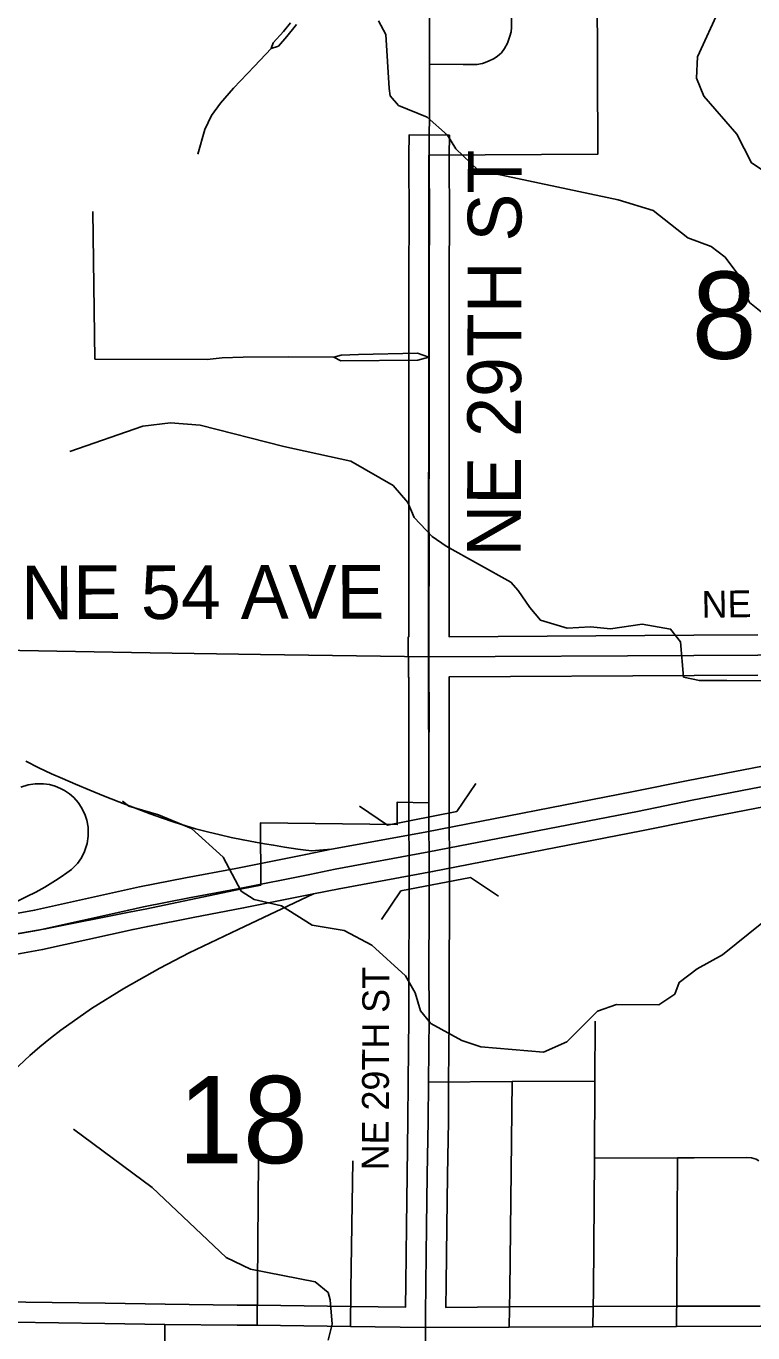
# Model space of a CAD drawing. Extents: x -1403959 to 81668, y -1400582 to 11018.
# Drawn here: x 7427.2 to 7531.9, y 8619.7 to 8808.1 of the extents above; entities that cross this region are included whole.
import ezdxf

# ---------------------------------------------------------------- set-up
doc = ezdxf.new("R2010")
doc.units = 0
for name, color, linetype in [('tdCiAirportTxt', 7, 'Continuous'), ('tdCiCityCartoShort', 7, 'Continuous'), ('tdCiCityDivCarto', 7, 'Continuous'), ('tdCiCoBndryTxt', 7, 'Continuous'), ('tdCiRRCL', 7, 'Continuous'), ('tdCiSectLine', 7, 'Continuous'), ('tdCiSectNmbr', 7, 'Continuous'), ('tdCiSectTwpRng', 7, 'Continuous'), ('tdCoPriCL', 7, 'Continuous'), ('tdCoSectLinePart', 7, 'Continuous'), ('tdCoSectNmbr', 7, 'Continuous'), ('tdCoSurfBitum', 7, 'Continuous'), ('tdCoSurfEarth', 7, 'Continuous')]:
    doc.layers.add(name, color=color, linetype=linetype)

msp = doc.modelspace()

# ---------------------------------------------------------------- linework, layer by layer
at = {"layer": 'tdCiAirportTxt'}
for points in [[(7416.8, 8678.77), (7423.36, 8679.72), (7428.41, 8680.61), (7441.36, 8683.49), (7443.53, 8683.97), (7450.14, 8685.25), (7457.39, 8686.63), (7467.46, 8688.65), (7471.16, 8689.39), (7484.66, 8691.88), (7514.67, 8697.73), (7522.55, 8699.33), (7547.93, 8704.23), (7560.49, 8706.69), (7568.14, 8708.19)], [(7416.8, 8672.91), (7424.28, 8673.99), (7429.55, 8674.92), (7442.6, 8677.83), (7444.7, 8678.28), (7451.24, 8679.55), (7458.5, 8680.93), (7468.6, 8682.95), (7472.26, 8683.69), (7485.74, 8686.18), (7515.8, 8692.04), (7523.68, 8693.64), (7549.04, 8698.53), (7561.6, 8701), (7570.86, 8702.8)]]:
    msp.add_lwpolyline(points, dxfattribs=at)
at = {"layer": 'tdCiCityCartoShort'}
msp.add_lwpolyline([(7581.35, 8707.79), (7561.04, 8703.82), (7548.48, 8701.35), (7523.11, 8696.45), (7515.23, 8694.86), (7485.19, 8689), (7471.7, 8686.51), (7468.03, 8685.77), (7457.94, 8683.75), (7450.69, 8682.37), (7444.11, 8681.09), (7441.98, 8680.63), (7428.98, 8677.74), (7423.8, 8676.82), (7414.4, 8675.33)], dxfattribs=at)
at = {"layer": 'tdCiCityDivCarto'}
for points in [[(7508.81, 8620.55), (7508.89, 8625.89), (7509.06, 8644.86), (7509.08, 8655.94), (7509.13, 8664.61)], [(7485.14, 8655.82), (7497.18, 8655.9), (7509.08, 8655.94)], [(7496.76, 8620.51), (7496.85, 8625.88), (7497.18, 8655.9)], [(7460.48, 8620.78), (7460.67, 8644.58)], [(7473.91, 8620.58), (7473.96, 8625.94), (7474.25, 8644.47)], [(7509.06, 8644.86), (7521.03, 8644.89)], [(7520.84, 8620.61), (7520.89, 8625.89), (7521.03, 8644.89)], [(7521.03, 8644.89), (7523.4, 8644.92), (7530.88, 8644.96), (7531.66, 8644.89), (7532.32, 8644.73), (7532.73, 8644.47)], [(7447.11, 8596.78), (7447.19, 8620.88)]]:
    msp.add_lwpolyline(points, dxfattribs=at)
at = {"layer": 'tdCiCoBndryTxt'}
for points in [[(7485.21, 8696.1), (7485.21, 8702.59), (7485.23, 8709.86), (7485.21, 8714.28), (7485.21, 8717.12), (7485.21, 8722.89), (7485.23, 8731.67), (7485.21, 8738.54), (7485.23, 8746.99), (7485.23, 8756.02), (7485.23, 8760.33), (7485.23, 8764.26), (7485.23, 8772.68), (7485.27, 8780.18), (7485.23, 8789.15), (7485.23, 8789.45)], [(7485.14, 8717.12), (7485.21, 8717.12), (7485.21, 8717.12)], [(7485.21, 8717.12), (7523.38, 8717.35), (7532.58, 8717.39), (7538.9, 8717.43), (7546.99, 8717.49), (7554.11, 8717.56), (7563.63, 8717.64), (7564.75, 8717.65)], [(7485.14, 8655.82), (7485.23, 8665.03), (7485.21, 8672.99), (7485.25, 8679.76), (7485.25, 8686.75), (7485.21, 8694.46), (7485.21, 8696.08)], [(7485.21, 8696.08), (7485.21, 8696.1)], [(7484.52, 8597.05), (7484.61, 8605.17), (7484.64, 8607.27), (7484.66, 8613.68), (7484.7, 8620.43), (7484.71, 8622.3), (7484.77, 8626.75), (7484.87, 8634.99), (7484.96, 8642.42), (7485.1, 8650.26), (7485.14, 8655.82)], [(7411.77, 8621.39), (7438.52, 8621.04), (7447.19, 8620.88), (7457.57, 8620.76), (7460.48, 8620.78)], [(7460.48, 8620.78), (7473.91, 8620.58), (7484.61, 8620.43), (7484.7, 8620.43), (7496.76, 8620.51), (7496.76, 8620.51)], [(7496.76, 8620.51), (7508.81, 8620.55), (7520.84, 8620.61), (7532.91, 8620.64), (7539, 8620.66), (7545.33, 8620.7)]]:
    msp.add_lwpolyline(points, dxfattribs=at)
at = {"layer": 'tdCiRRCL'}
msp.add_lwpolyline([(7509.45, 8813.97), (7509.55, 8789.62), (7485.18, 8789.45), (7485.2, 8770.43), (7485.14, 8717.12), (7485.21, 8696.09), (7480.63, 8696.16), (7480.65, 8692.94), (7460.96, 8693.21), (7461, 8684.24), (7458, 8683.64), (7444.59, 8680.81), (7442.02, 8680.32), (7430, 8677.92), (7423.86, 8676.86)], dxfattribs=at)
at = {"layer": 'tdCiSectLine'}
for points in [[(7411.81, 8624.29), (7438.56, 8623.94), (7438.58, 8623.94), (7447.23, 8623.79), (7457.58, 8623.66), (7460.47, 8623.68), (7460.48, 8623.68), (7460.52, 8623.68), (7473.95, 8623.48), (7481.83, 8623.37), (7481.87, 8626.79), (7481.97, 8635.03), (7481.97, 8635.03), (7482.06, 8642.45), (7482.06, 8642.47), (7482.19, 8650.3), (7482.23, 8655.84), (7482.23, 8655.85), (7482.33, 8665.04), (7482.31, 8672.98), (7482.31, 8672.99), (7482.31, 8673), (7482.35, 8679.77), (7482.35, 8686.74), (7482.31, 8694.44), (7482.31, 8694.46), (7482.31, 8702.59), (7482.31, 8702.59), (7482.33, 8709.85), (7482.31, 8714.21), (7482.26, 8714.2), (7482.22, 8720.01), (7482.31, 8720.01), (7482.31, 8722.89), (7482.31, 8722.9), (7482.33, 8731.67), (7482.31, 8738.53), (7482.31, 8738.54), (7482.31, 8738.54), (7482.33, 8747), (7482.33, 8772.68), (7482.33, 8772.69), (7482.37, 8780.18), (7482.33, 8789.13), (7482.33, 8789.15), (7482.33, 8789.17), (7482.33, 8789.47), (7482.35, 8792.37), (7488.15, 8792.33), (7488.13, 8789.43), (7488.13, 8789.14), (7488.17, 8780.19), (7488.17, 8780.18), (7488.17, 8780.16), (7488.13, 8772.67), (7488.13, 8746.99), (7488.13, 8746.99), (7488.11, 8738.54), (7488.13, 8731.68), (7488.13, 8731.67), (7488.13, 8731.66), (7488.11, 8722.89), (7488.11, 8720.04), (7523.36, 8720.26), (7523.37, 8720.26), (7532.57, 8720.29)], [(7532.6, 8714.49), (7523.39, 8714.45), (7488.11, 8714.24), (7488.13, 8709.87), (7488.13, 8709.86), (7488.13, 8709.85), (7488.11, 8702.58), (7488.11, 8694.46), (7488.15, 8686.76), (7488.15, 8686.75), (7488.15, 8679.76), (7488.15, 8679.75), (7488.11, 8672.98), (7488.13, 8665.04), (7488.13, 8665.03), (7488.13, 8665), (7488.04, 8655.79), (7488, 8650.24), (7488, 8650.21), (7487.86, 8642.37), (7487.77, 8634.96), (7487.67, 8626.72), (7487.67, 8626.71), (7487.63, 8623.35), (7496.74, 8623.41), (7496.75, 8623.41), (7508.79, 8623.45), (7520.82, 8623.51), (7520.83, 8623.51), (7532.9, 8623.54)]]:
    msp.add_lwpolyline(points, dxfattribs=at)
at = {"layer": 'tdCiSectNmbr'}
for points in [[(7485.23, 8789.45), (7485.29, 8797.79), (7485.29, 8806.23), (7485.27, 8813.54), (7485.26, 8819.39), (7485.31, 8826.12), (7485.3, 8834.03), (7485.31, 8841.54), (7485.31, 8841.67)], [(7415.46, 8718.22), (7445.06, 8717.71), (7460.95, 8717.48)]]:
    msp.add_lwpolyline(points, dxfattribs=at)
at = {"layer": 'tdCiSectTwpRng'}
for points in [[(7485.29, 8802.6), (7490.12, 8802.52), (7492.12, 8802.51), (7492.94, 8802.68), (7493.8, 8803), (7494.6, 8803.39), (7495.09, 8803.72), (7495.64, 8804.23), (7496.07, 8804.84), (7496.51, 8805.62), (7496.86, 8806.6), (7497.05, 8807.23), (7497.08, 8807.87), (7497.13, 8813.75)], [(7465.27, 8808.55), (7464.25, 8807.27), (7462.77, 8805.67), (7462.48, 8804.82)], [(7462.48, 8804.82), (7463.52, 8805.16), (7464.74, 8806.55), (7465.96, 8808.04), (7466.11, 8808.3)], [(7460.06, 8802.27), (7462.48, 8804.82)], [(7451.9, 8789.59), (7452.92, 8793.16), (7453.87, 8795.16), (7455.18, 8796.98), (7457.07, 8799.13), (7460.06, 8802.27)], [(7437.07, 8760.06), (7436.78, 8781.34)], [(7453.27, 8760), (7455.44, 8760.24), (7458.43, 8760.34), (7464.91, 8760.38), (7471.53, 8760.35)], [(7485.2, 8760.34), (7483.57, 8760.93), (7475.04, 8760.71), (7472.56, 8760.64), (7471.53, 8760.35)], [(7471.53, 8760.35), (7472.51, 8759.83), (7483.6, 8759.93), (7485.19, 8760.32)], [(7485.19, 8760.32), (7485.23, 8760.33)], [(7485.23, 8760.33), (7485.2, 8760.34)], [(7437.07, 8760.06), (7453.27, 8760)], [(7460.95, 8717.48), (7485.14, 8717.12)]]:
    msp.add_lwpolyline(points, dxfattribs=at)
at = {"layer": 'tdCoPriCL'}
for points in [[(7471.16, 8689.39), (7468.27, 8689.15), (7467.07, 8689.32), (7466.34, 8689.42), (7465.37, 8689.56), (7464.41, 8689.71), (7462.82, 8689.96), (7461.54, 8690.18), (7460.22, 8690.41), (7458.44, 8690.75), (7456.72, 8691.11), (7455.12, 8691.46), (7453.32, 8691.9), (7451.59, 8692.36), (7450.18, 8692.77), (7448.49, 8693.29), (7446.71, 8693.9), (7445.04, 8694.5), (7443.18, 8695.2), (7440.53, 8696.22), (7438.32, 8697.11), (7436.36, 8697.91), (7434.31, 8698.77), (7432.43, 8699.59), (7430.86, 8700.29), (7429.04, 8701.14), (7427.13, 8702.07)], [(7426.42, 8698.34), (7427.5, 8698.69), (7428.5, 8698.84), (7429.68, 8698.84), (7430.57, 8698.71), (7431.37, 8698.49), (7432.15, 8698.17), (7432.72, 8697.87), (7433.43, 8697.38), (7434.05, 8696.84), (7434.69, 8696.12), (7435.22, 8695.33), (7435.69, 8694.33), (7435.93, 8693.58), (7436.12, 8692.56), (7436.14, 8691.3), (7435.97, 8690.2), (7435.62, 8689.09), (7435.15, 8688.17), (7434.57, 8687.35), (7433.72, 8686.46), (7433.03, 8685.99), (7432.23, 8685.44), (7431.41, 8684.9), (7429.86, 8683.94), (7428.58, 8683.22), (7427.29, 8682.56), (7425.96, 8681.93)], [(7414.79, 8638.47), (7416, 8642.66), (7417.35, 8646.04), (7418.7, 8648.68), (7420.16, 8651.08), (7420.85, 8652.08), (7421.37, 8652.79), (7422.08, 8653.71), (7422.84, 8654.65), (7424.14, 8656.13), (7426.12, 8658.17), (7427.74, 8659.68), (7429.16, 8660.91), (7430.68, 8662.15), (7432.19, 8663.33), (7436.6, 8666.42), (7441.24, 8669.31), (7446.44, 8672.24), (7450.68, 8674.44), (7457.71, 8677.81), (7468.6, 8682.95)]]:
    msp.add_lwpolyline(points, dxfattribs=at)
at = {"layer": 'tdCoSurfBitum'}
for points in [[(7535.34, 8765.6), (7534.57, 8769.57), (7535.19, 8771.4), (7536.87, 8773.99), (7541.15, 8777.81), (7542.52, 8780.25), (7542.98, 8782.23), (7542.83, 8785.9), (7541.61, 8787.43), (7540.54, 8788.19), (7537.33, 8787.89), (7535.35, 8786.97), (7533.06, 8787.43), (7531.68, 8788.35), (7529.55, 8792.47), (7524.81, 8797.97), (7523.75, 8800.57), (7523.9, 8803.62), (7527.11, 8810.64)], [(7477.94, 8808.84), (7479.01, 8806.86), (7479.46, 8799.07), (7479.61, 8798), (7480.83, 8796.63), (7484.96, 8794.95), (7487.86, 8792.35), (7489.08, 8790.36), (7492.28, 8787.31), (7512.44, 8783.02), (7517.48, 8781.49), (7522.51, 8777.52), (7525.87, 8776.29), (7527.86, 8774.76), (7529.69, 8772.32), (7529.69, 8771.71), (7531.37, 8768.2), (7534.27, 8765.9)], [(7558.81, 8713.67), (7528.1, 8713.74), (7524.16, 8713.7), (7521.88, 8714.22), (7521.43, 8719.32), (7520.01, 8721.13), (7515.94, 8721.84), (7511.36, 8721.19), (7508.46, 8721.45), (7505.1, 8721.26), (7501.26, 8722.41), (7499.73, 8724.25), (7498.06, 8726.69), (7496.99, 8727.91), (7487.67, 8733.11), (7485.69, 8734.49), (7483.1, 8737.24), (7482.18, 8739.38), (7480.04, 8741.82), (7473.94, 8745.34), (7464.32, 8747.48), (7452.25, 8750.54), (7447.98, 8750.85), (7444.01, 8750.39), (7433.47, 8746.74)], [(7533.16, 8678.73), (7527.5, 8674.15), (7523.84, 8672.17), (7521.24, 8670.19), (7520.63, 8668.51), (7518.34, 8666.98), (7512.23, 8666.99), (7509.48, 8666.07), (7505.05, 8661.65), (7501.69, 8660.12), (7492.68, 8660.89), (7489.93, 8661.81), (7485.5, 8664.26), (7483.98, 8666.09), (7483.21, 8668.69), (7481.84, 8671.13), (7476.96, 8675.56), (7472.99, 8677.7), (7468.41, 8678.47), (7463.98, 8681.22), (7460.01, 8682.14), (7458.18, 8683.36), (7455.58, 8688.25), (7451, 8692.37), (7446.27, 8694.36), (7442, 8695.59), (7441.08, 8696.35)], [(7434.03, 8649.02), (7445.33, 8640.62), (7456.01, 8630.54), (7459.52, 8628.85), (7468.84, 8627.01), (7470.67, 8625.49), (7470.98, 8624.42), (7471.28, 8620.91), (7470.67, 8618.62)]]:
    msp.add_lwpolyline(points, dxfattribs=at)
at = {"layer": 'tdCoSurfEarth'}
for p, q in [((7489.23, 8694.82), (7491.95, 8698.86)), ((7479.25, 8692.88), (7475.21, 8695.6)), ((7479.25, 8692.88), (7489.23, 8694.82)), ((7491.17, 8685.34), (7481.17, 8683.39)), ((7491.17, 8685.34), (7495.21, 8682.62)), ((7481.17, 8683.39), (7478.39, 8679.27))]:
    msp.add_line(p, q, dxfattribs=at)

# ---------------------------------------------------------------- texts
at = {"layer": 'tdCoSectLinePart'}
for s, height, rotation, p in [('8', 12.57, 359.9979, (7523.05, 8760.11)), ('18', 12.575, 359.9974, (7449.07, 8644.13))]:
    msp.add_text(s, height=height, rotation=rotation, dxfattribs=at).set_placement(p)
at = {"layer": 'tdCoSectNmbr'}
for s, height, rotation, p in [('NE 29TH ST', 7.738, 89.8805, (7498.43, 8731.58)), ('NE 54 AVE', 7.738, 0.1064, (7426.48, 8722.55)), ('NE 54 PL', 3.869, 0.8258, (7524.5, 8722.76)), ('NE 29TH ST', 3.869, 89.8012, (7479.4, 8643.09))]:
    msp.add_text(s, height=height, rotation=rotation, dxfattribs=at).set_placement(p)

doc.saveas('drawing.dxf')
